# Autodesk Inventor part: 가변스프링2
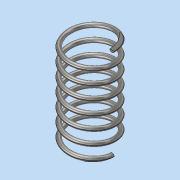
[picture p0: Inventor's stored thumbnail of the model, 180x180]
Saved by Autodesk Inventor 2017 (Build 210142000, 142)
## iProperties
Part Number: 가변스프링2
Material: 스테인레스 스틸
Document SubType Name: Modeling
Designer: MRC
Density: 8 g/cm^3
Appearance: 반연마
Mass: 10.9602 g
Surface Area: 27.6886 cm^2
Volume: 1.37003 cm^3
Author: MRC
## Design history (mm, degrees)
sketch "스케치1"
  geometry: L1 (0, 0)-(10, 0); L2 (10, 0)-(10, 41.411); L3 (10, 41.411)-(0, 41.411); L4 (0, 41.411)-(0, 0); C1 r 1 at (10, 0)
  constraints: 8 end point, 2 parallel, 1 centre point, 1 coincident, 1 horizontal, 1 perpendicular
  dimensions: "d0" = 20 diameter of L2 L4; "d1" = 41.4112 distance of L1.end L2.end (derived); "d2" = 2 diameter of C1
feature "코일1" sketch "스케치1" pitch "d3" = 10; turns "d5" = 7; dims "d4" = 41.4112 (= d1), "d6" = 0, angle "d7" = 90 deg, angle "d8" = 90 deg, "d9" = 0, "d10" = 0
sketch "스케치2"
  geometry: L1 (-15, 41.411)-(15, 41.411); L2 (15, 41.411)-(15, 0); L3 (15, 0)-(-15, 0); L4 (-15, 0)-(-15, 41.411); L5 (0, 41.411)-(0, 0) reference; 2 further points
  constraints: 8 end point, 2 midpoint, 2 parallel, 1 coincident, 1 horizontal, 1 perpendicular
  dimensions: "d11" = 30 distance of L1.start L1.end
extrude "돌출1" sketch "스케치2" stored distance "d12" = 0; taper "d13" = 0 deg
node "솔리드1"
